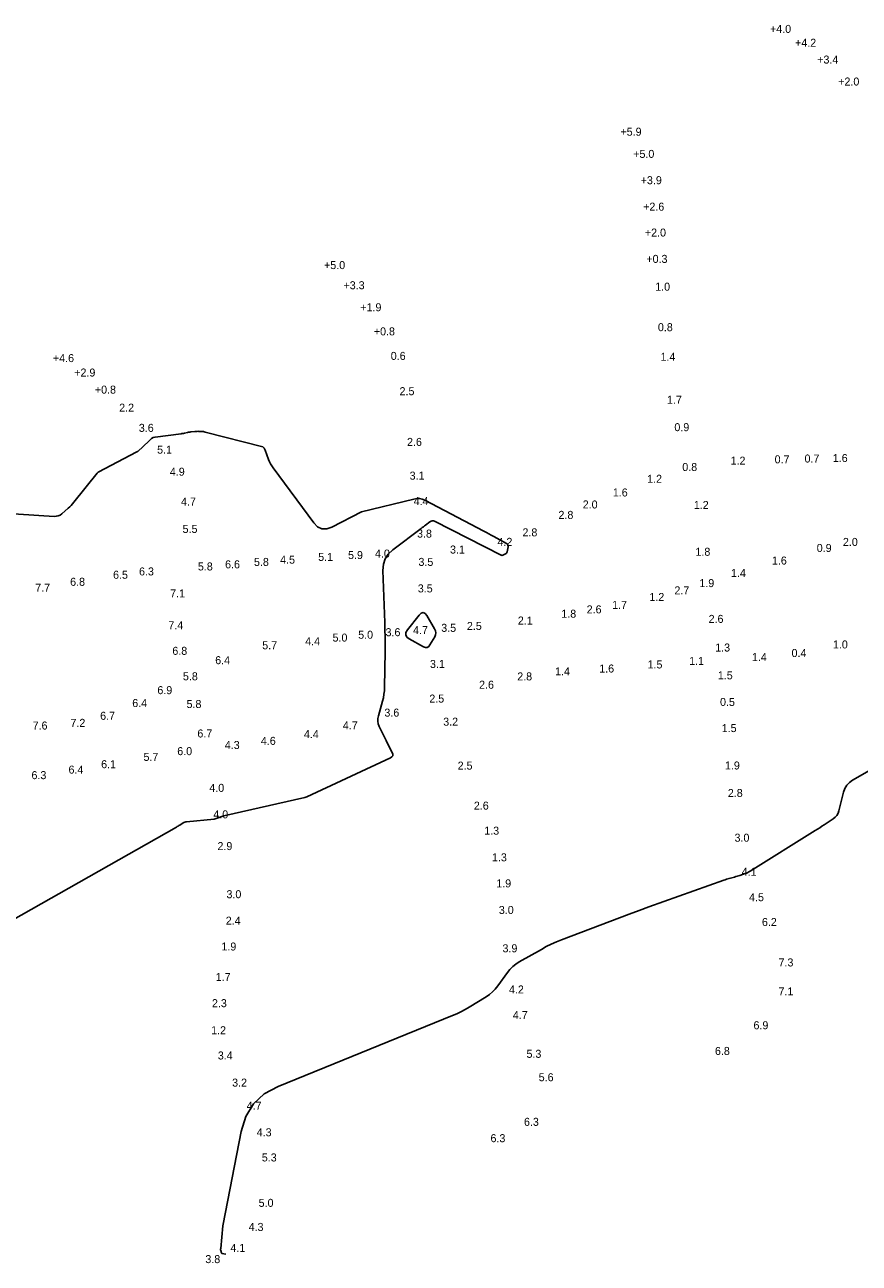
# Model space of a CAD drawing. Extents: x 837127 to 848654, y 3074248 to 3079868.
# Drawn here: x 846483.6 to 846809.6, y 3078132.8 to 3078616.4 of the extents above; entities that cross this region are included whole.
import ezdxf

# ---------------------------------------------------------------- set-up
doc = ezdxf.new("R2010")
doc.units = 0
doc.layers.add('V-HYDS-MAJR', color=7, linetype='Continuous')
doc.layers.add('V-HYDS-SOUN', color=7, linetype='Continuous')

msp = doc.modelspace()

# ---------------------------------------------------------------- linework, layer by layer
at = {"layer": 'V-HYDS-MAJR'}
for points in [[(846435.32, 3078428.26), (846495.09, 3078424.46), (846495.89, 3078424.48), (846496.64, 3078424.66), (846497.35, 3078424.97), (846498, 3078425.44), (846500.51, 3078427.61), (846501.12, 3078428.17), (846501.71, 3078428.75), (846502.27, 3078429.36), (846502.8, 3078430), (846511.91, 3078441.38), (846512.29, 3078441.74), (846527.35, 3078449.59), (846527.54, 3078449.74), (846527.75, 3078449.83), (846532.09, 3078453.77), (846532.54, 3078454.4), (846533.1, 3078454.88), (846533.75, 3078455.21), (846534.5, 3078455.39), (846544.67, 3078456.71), (846544.98, 3078456.75), (846545.3, 3078456.8), (846545.61, 3078456.86), (846545.92, 3078456.93), (846547.17, 3078457.21), (846547.48, 3078457.27), (846547.79, 3078457.33), (846548.11, 3078457.38), (846548.42, 3078457.42), (846550.05, 3078457.59), (846550.42, 3078457.63), (846550.8, 3078457.65), (846551.18, 3078457.66), (846551.55, 3078457.65), (846553.34, 3078457.58), (846553.72, 3078457.52), (846554.02, 3078457.35), (846576.54, 3078451.6), (846577.1, 3078451.08), (846577.51, 3078450.31), (846578.8, 3078446.69), (846579.16, 3078445.8), (846579.58, 3078444.95), (846580.06, 3078444.13), (846580.6, 3078443.34), (846596.5, 3078421.9), (846598, 3078420.37), (846599.68, 3078419.58), (846601.53, 3078419.55), (846603.56, 3078420.26), (846615.17, 3078426.26), (846635.62, 3078431.13), (846636.72, 3078431.39), (846637.81, 3078431.43), (846638.88, 3078431.23), (846639.93, 3078430.79), (846662.95, 3078418.65), (846663.92, 3078418.14), (846664.88, 3078417.63), (846665.85, 3078417.11), (846666.81, 3078416.59), (846671.8, 3078413.88), (846672.13, 3078413.64), (846672.34, 3078413.35), (846672.43, 3078413), (846672.41, 3078412.6), (846672.02, 3078410.57), (846671.94, 3078410.31), (846671.8, 3078410.09), (846671.62, 3078409.91), (846671.38, 3078409.77), (846670.31, 3078409.3), (846670.06, 3078409.23), (846669.84, 3078409.25), (846669.64, 3078409.36), (846643.69, 3078422.6), (846643.21, 3078422.74), (846642.74, 3078422.75), (846642.29, 3078422.62), (846641.86, 3078422.36), (846640.17, 3078421.04), (846639.74, 3078420.71), (846639.32, 3078420.39), (846638.89, 3078420.06), (846638.46, 3078419.74), (846627.34, 3078411.37), (846625.6, 3078409.74), (846624.38, 3078407.86), (846623.69, 3078405.74), (846623.51, 3078403.36), (846624.21, 3078382.97), (846624.29, 3078380.17), (846624.33, 3078377.37), (846624.35, 3078374.56), (846624.32, 3078371.76), (846624.12, 3078357.67), (846624.06, 3078356.31), (846623.91, 3078354.96), (846623.67, 3078353.63), (846623.34, 3078352.31), (846621.72, 3078346.62), (846621.51, 3078345.54), (846621.51, 3078344.47), (846621.7, 3078343.43), (846622.09, 3078342.4), (846624.38, 3078337.65), (846624.72, 3078336.96), (846625.05, 3078336.27), (846625.4, 3078335.59), (846625.74, 3078334.91), (846627.14, 3078332.18), (846627.35, 3078331.55), (846627.31, 3078331), (846627.01, 3078330.54), (846626.45, 3078330.18), (846593.82, 3078314.94), (846592.96, 3078314.67), (846561.34, 3078307.56), (846558.69, 3078306.54), (846557.58, 3078306.26), (846546.82, 3078305.19), (846546.45, 3078305.14), (846546.1, 3078305.04), (846545.76, 3078304.9), (846545.43, 3078304.72), (846544.15, 3078303.92), (846543.83, 3078303.72), (846543.5, 3078303.52), (846543.18, 3078303.33), (846542.85, 3078303.14), (846478.27, 3078266.46)], [(846816.4, 3078326.83), (846807, 3078321.46), (846805.74, 3078320.57), (846804.73, 3078319.49), (846803.97, 3078318.23), (846803.45, 3078316.77), (846801.64, 3078309.5), (846801.31, 3078308.54), (846800.82, 3078307.69), (846800.18, 3078306.95), (846799.39, 3078306.32), (846795.9, 3078304.02), (846795.02, 3078303.44), (846794.15, 3078302.88), (846793.27, 3078302.31), (846792.38, 3078301.76), (846766.97, 3078285.89), (846766.5, 3078285.62), (846766.02, 3078285.37), (846765.52, 3078285.16), (846765.02, 3078284.96), (846762.96, 3078284.26), (846762.44, 3078284.08), (846761.92, 3078283.92), (846761.4, 3078283.77), (846760.88, 3078283.62), (846758.74, 3078283.04), (846758.21, 3078282.89), (846757.68, 3078282.73), (846757.16, 3078282.56), (846756.64, 3078282.38), (846727.4, 3078271.91), (846723.56, 3078270.53), (846719.73, 3078269.13), (846715.91, 3078267.7), (846712.09, 3078266.26), (846693.31, 3078259.11), (846691.28, 3078258.29), (846689.29, 3078257.39), (846687.33, 3078256.42), (846685.41, 3078255.37), (846676.76, 3078250.44), (846675.44, 3078249.59), (846674.22, 3078248.61), (846673.11, 3078247.51), (846672.12, 3078246.28), (846668.37, 3078241.11), (846667.38, 3078239.88), (846666.29, 3078238.76), (846665.08, 3078237.75), (846663.78, 3078236.86), (846657.15, 3078232.78), (846655.57, 3078231.86), (846653.96, 3078231), (846652.32, 3078230.21), (846650.64, 3078229.49), (846582.53, 3078201.83), (846577.13, 3078198.9), (846572.92, 3078195), (846569.9, 3078190.12), (846568.07, 3078184.26), (846561.03, 3078148.08), (846560.93, 3078147.34), (846560.15, 3078138.54), (846560.1, 3078138.34), (846560.08, 3078138.13), (846560.09, 3078137.93), (846560.14, 3078137.73), (846560.41, 3078136.91), (846560.49, 3078136.74), (846560.6, 3078136.64), (846562.08, 3078136.28)]]:
    msp.add_lwpolyline(points, dxfattribs=at)
msp.add_lwpolyline([(846639.23, 3078386.89), (846639.95, 3078386.57), (846640.63, 3078385.71), (846643.7, 3078380.55), (846644.05, 3078379.76), (846644.17, 3078378.98), (846644.06, 3078378.19), (846643.72, 3078377.4), (846641.88, 3078374.25), (846641.38, 3078373.62), (846640.79, 3078373.29), (846640.12, 3078373.27), (846639.36, 3078373.55), (846633.76, 3078376.62), (846632.82, 3078377.33), (846632.39, 3078378.15), (846632.47, 3078379.07), (846633.06, 3078380.09), (846637.68, 3078385.91), (846638.47, 3078386.67)], close=True, dxfattribs=at)

# ---------------------------------------------------------------- texts
at = {"layer": 'V-HYDS-SOUN'}
for s, p in [('+4.0 ', (846774.73, 3078613.25)), ('+4.2 ', (846784.52, 3078607.84)), ('+3.4 ', (846793.17, 3078601.27)), ('+2.0 ', (846801.38, 3078592.68)), ('+5.9 ', (846716.3, 3078573.1)), ('+5.0 ', (846721.29, 3078564.43)), ('+3.9 ', (846724.21, 3078554.16)), ('+2.6 ', (846725.16, 3078543.82)), ('+2.0 ', (846725.85, 3078533.71)), ('+0.3 ', (846726.43, 3078523.43)), ('+5.0 ', (846600.5, 3078521.01)), ('+3.3 ', (846608.09, 3078513.14)), ('1.0', (846729.88, 3078512.57)), ('+1.9 ', (846614.66, 3078504.54)), ('+0.8 ', (846619.95, 3078495.13)), ('0.8', (846730.93, 3078496.76)), ('+4.6 ', (846494.58, 3078484.69)), ('0.6', (846626.56, 3078485.55)), ('1.4', (846731.95, 3078485.21)), ('+2.9 ', (846502.91, 3078479.05)), ('+0.8 ', (846510.96, 3078472.38)), ('2.5', (846630, 3078471.77)), ('2.2', (846520.47, 3078465.34)), ('1.7', (846734.49, 3078468.42)), ('3.6', (846528.14, 3078457.45)), ('0.9', (846737.37, 3078457.72)), ('2.6', (846632.92, 3078451.96)), ('5.1', (846535.28, 3078448.94)), ('0.7', (846776.54, 3078445.16)), ('0.7', (846788.22, 3078445.47)), ('1.6', (846799.26, 3078445.67)), ('4.9', (846540.26, 3078440.33)), ('0.8', (846740.46, 3078442.17)), ('1.2', (846759.33, 3078444.65)), ('3.1', (846633.93, 3078438.79)), ('1.2', (846726.72, 3078437.55)), ('1.6', (846713.32, 3078432.22)), ('4.7', (846544.65, 3078428.68)), ('4.4', (846635.49, 3078428.83)), ('2.0', (846701.56, 3078427.54)), ('1.2', (846744.97, 3078427.34)), ('2.8', (846692.09, 3078423.46)), ('5.5', (846545.24, 3078417.98)), ('3.8', (846636.83, 3078416.16)), ('2.8', (846678.02, 3078416.64)), ('4.2', (846668.26, 3078412.93)), ('2.0', (846803.21, 3078412.9)), ('5.1', (846598.21, 3078407.05)), ('5.9', (846609.88, 3078407.78)), ('4.0', (846620.41, 3078408.36)), ('3.1', (846649.72, 3078409.94)), ('1.8', (846745.6, 3078409.07)), ('0.9', (846792.99, 3078410.55)), ('5.8', (846551.21, 3078403.33)), ('6.6', (846561.84, 3078404.15)), ('5.8', (846573.13, 3078405.09)), ('4.5', (846583.34, 3078405.98)), ('3.5', (846637.38, 3078405.11)), ('1.6', (846775.48, 3078405.63)), ('6.8', (846501.3, 3078397.34)), ('6.5', (846518.07, 3078400.09)), ('6.3', (846528.22, 3078401.38)), ('1.9', (846747.13, 3078396.83)), ('1.4', (846759.49, 3078400.76)), ('7.7', (846487.68, 3078395.03)), ('7.1', (846540.38, 3078392.81)), ('3.5', (846637.13, 3078394.75)), ('2.7', (846737.39, 3078393.98)), ('1.7', (846713.06, 3078388.31)), ('1.2', (846727.6, 3078391.41)), ('1.8', (846693.2, 3078384.87)), ('2.6', (846703.1, 3078386.57)), ('2.6', (846750.75, 3078382.85)), ('7.4', (846539.67, 3078380.36)), ('3.6', (846624.53, 3078377.65)), ('4.7', (846635.27, 3078378.45)), ('3.5', (846646.28, 3078379.36)), ('2.5', (846656.31, 3078380.09)), ('2.1', (846676.21, 3078382.2)), ('4.4', (846593.14, 3078374.13)), ('5.0', (846603.82, 3078375.55)), ('5.0', (846613.83, 3078376.66)), ('1.0', (846799.32, 3078372.87)), ('6.8', (846541.23, 3078370.38)), ('5.7', (846576.35, 3078372.54)), ('1.3', (846753.32, 3078371.67)), ('1.4', (846767.67, 3078367.94)), ('0.4', (846783.15, 3078369.53)), ('6.4', (846557.98, 3078366.72)), ('3.1', (846641.88, 3078365.25)), ('1.6', (846708.01, 3078363.46)), ('1.5', (846726.89, 3078365.06)), ('1.1', (846743.14, 3078366.43)), ('5.8', (846545.37, 3078360.44)), ('2.8', (846675.98, 3078360.39)), ('1.4', (846690.76, 3078362.36)), ('1.5', (846754.35, 3078360.81)), ('6.9', (846535.38, 3078355.02)), ('2.6', (846661.07, 3078357.14)), ('6.4', (846525.57, 3078349.99)), ('5.8', (846546.78, 3078349.61)), ('2.5', (846641.63, 3078351.74)), ('0.5', (846755.21, 3078350.41)), ('6.7', (846513.03, 3078345.02)), ('3.6', (846624.08, 3078346.25)), ('7.6', (846486.65, 3078341.2)), ('7.2', (846501.43, 3078342.25)), ('4.7', (846607.84, 3078341.27)), ('3.2', (846647.06, 3078342.71)), ('1.5', (846755.87, 3078340.21)), ('6.7', (846551.01, 3078338.1)), ('4.6', (846575.82, 3078335.22)), ('4.4', (846592.63, 3078337.84)), ('6.0', (846543.15, 3078331.2)), ('4.3', (846561.72, 3078333.6)), ('6.1', (846513.41, 3078326.1)), ('5.7', (846529.96, 3078328.97)), ('2.5', (846652.69, 3078325.55)), ('1.9', (846757.13, 3078325.61)), ('6.3', (846486.2, 3078321.83)), ('6.4', (846500.67, 3078323.99)), ('4.0', (846555.68, 3078316.87)), ('2.8', (846758.26, 3078314.87)), ('2.6', (846659.03, 3078309.93)), ('4.0', (846557.25, 3078306.52)), ('1.3', (846663.09, 3078300.15)), ('3.0', (846760.87, 3078297.4)), ('2.9', (846558.86, 3078294.13)), ('1.3', (846666.11, 3078289.74)), ('4.1', (846763.64, 3078284.11)), ('1.9', (846667.79, 3078279.57)), ('3.0', (846562.38, 3078275.33)), ('4.5', (846766.56, 3078274.17)), ('3.0', (846668.79, 3078269.19)), ('2.4', (846562.1, 3078265.01)), ('6.2', (846771.57, 3078264.48)), ('1.9', (846560.4, 3078254.92)), ('3.9', (846670.22, 3078254.22)), ('7.3', (846778.06, 3078248.7)), ('1.7', (846558.18, 3078243.02)), ('4.2', (846672.74, 3078238.14)), ('7.1', (846778.06, 3078237.4)), ('2.3', (846556.71, 3078232.79)), ('4.7', (846674.26, 3078228.14)), ('6.9', (846768.28, 3078224.16)), ('1.2', (846556.39, 3078222.22)), ('5.3', (846679.59, 3078213.01)), ('6.8', (846753.22, 3078214.13)), ('3.4', (846558.99, 3078212.36)), ('5.6', (846684.36, 3078203.86)), ('3.2', (846564.59, 3078201.77)), ('4.7', (846570.26, 3078192.75)), ('6.3', (846678.61, 3078186.45)), ('4.3', (846574.19, 3078182.37)), ('6.3', (846665.53, 3078180.06)), ('5.3', (846576.18, 3078172.54)), ('5.0', (846574.95, 3078154.81)), ('4.3', (846571.04, 3078145.4)), ('4.1', (846563.93, 3078137.24)), ('3.8', (846554.13, 3078132.84))]:
    msp.add_text(s, height=3.125, dxfattribs=at).set_placement(p)

doc.saveas('drawing.dxf')
